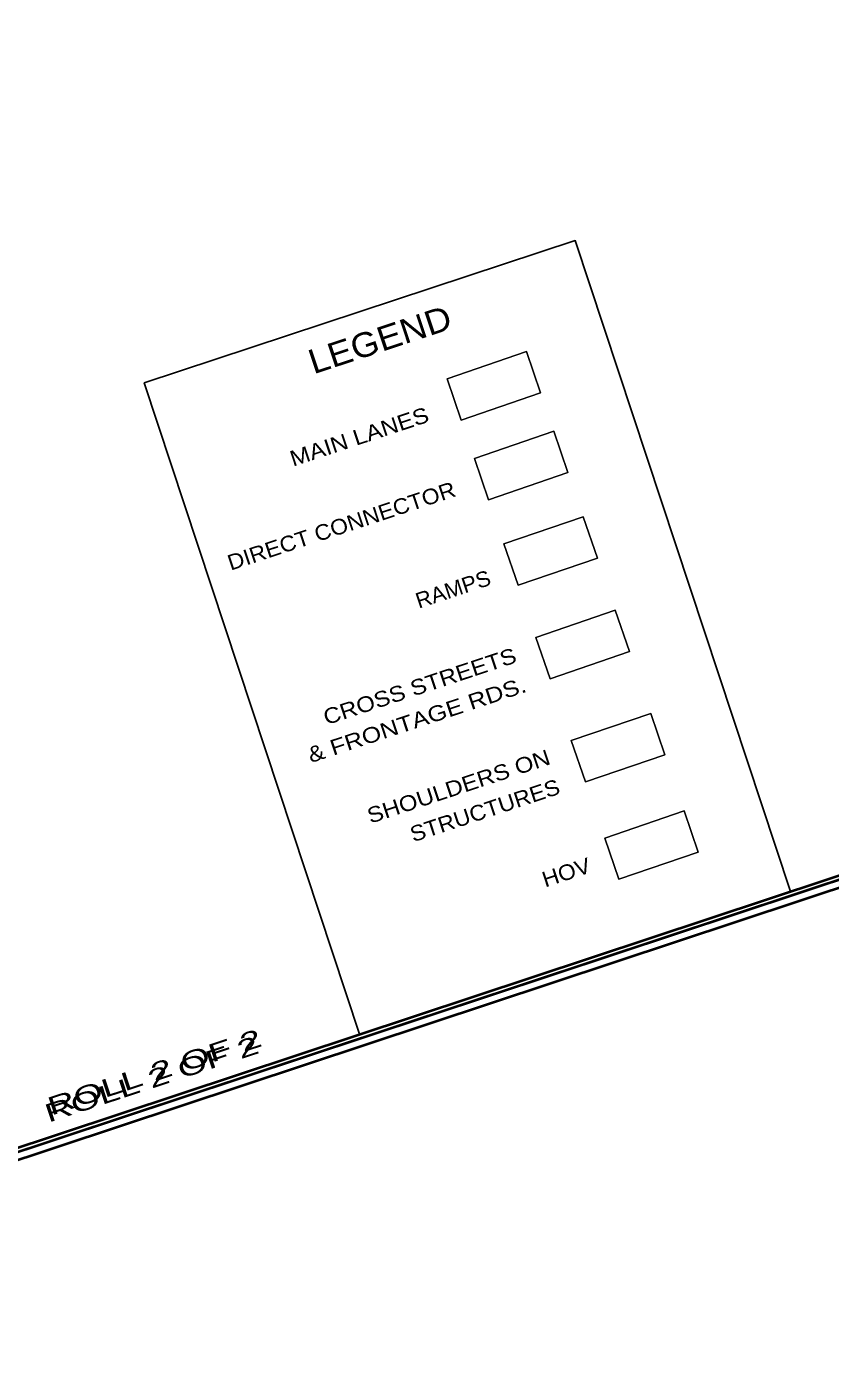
# Model space of a CAD drawing. Extents: x 2355803 to 2371254, y 6970215 to 6985302.
# Drawn here: x 2357680 to 2358715, y 6973568 to 6975290 of the extents above; entities that cross this region are included whole.
import ezdxf
from ezdxf.enums import TextEntityAlignment as Align

# ---------------------------------------------------------------- set-up
doc = ezdxf.new("R2010")
doc.units = 0
doc.header["$LTSCALE"] = 7.1
doc.layers.add('19', color=7, linetype='Continuous', lineweight=13)
doc.layers.add('8', color=7, linetype='Continuous', lineweight=13)

msp = doc.modelspace()

# ---------------------------------------------------------------- linework, layer by layer
at = {"layer": '19', "lineweight": 40}
msp.add_lwpolyline([(2371235.04, 6978344.083), (2356889.216, 6973586.555), (2355819.061, 6976813.747)], dxfattribs=at)
at = {"layer": '19', "lineweight": 25}
msp.add_lwpolyline([(2358108.756, 6973991.841), (2358663.88, 6974175.369), (2358386.548, 6975014.227), (2357831.424, 6974830.701)], close=True, dxfattribs=at)
at = {"layer": '19'}
for points in [[(2358323.762, 6974871.201), (2358342.014, 6974817.979), (2358239.818, 6974782.929), (2358221.564, 6974836.151)], [(2358221.564, 6974836.151), (2358239.818, 6974782.929), (2358342.014, 6974817.979), (2358323.762, 6974871.201)], [(2358358.966, 6974768.557), (2358377.22, 6974715.337), (2358275.02, 6974680.285), (2358256.768, 6974733.507)], [(2358256.768, 6974733.507), (2358275.02, 6974680.285), (2358377.22, 6974715.337), (2358358.966, 6974768.557)], [(2358396.778, 6974658.309), (2358415.03, 6974605.089), (2358312.832, 6974570.037), (2358294.578, 6974623.259)], [(2358294.578, 6974623.259), (2358312.832, 6974570.037), (2358415.03, 6974605.089), (2358396.778, 6974658.309)], [(2358438.066, 6974537.925), (2358456.318, 6974484.705), (2358354.122, 6974449.653), (2358335.868, 6974502.875)], [(2358335.868, 6974502.875), (2358354.122, 6974449.653), (2358456.318, 6974484.705), (2358438.066, 6974537.925)], [(2358483.7, 6974404.871), (2358501.954, 6974351.649), (2358399.754, 6974316.599), (2358381.5, 6974369.821)], [(2358381.5, 6974369.821), (2358399.754, 6974316.599), (2358501.954, 6974351.649), (2358483.7, 6974404.871)], [(2358526.726, 6974279.417), (2358544.98, 6974226.195), (2358442.782, 6974191.145), (2358424.53, 6974244.367)], [(2358424.53, 6974244.367), (2358442.782, 6974191.145), (2358544.98, 6974226.195), (2358526.726, 6974279.417)]]:
    msp.add_lwpolyline(points, close=True, dxfattribs=at)
at = {"layer": '8', "lineweight": 40}
for p, q in [((2371241.36, 6978340.911), (2356886.044, 6973580.235)), ((2371231.868, 6978337.763), (2356886.044, 6973580.235)), ((2371254, 6978334.567), (2356879.7, 6973567.595))]:
    msp.add_line(p, q, dxfattribs=at)
at = {"layer": '8', "lineweight": 25}
msp.add_lwpolyline([(2358108.756, 6973991.841), (2358663.88, 6974175.369), (2358386.548, 6975014.227), (2357831.424, 6974830.701)], close=True, dxfattribs=at)
at = {"layer": '8'}
for points in [[(2358323.762, 6974871.201), (2358342.014, 6974817.979), (2358239.818, 6974782.929), (2358221.564, 6974836.151)], [(2358221.564, 6974836.151), (2358239.818, 6974782.929), (2358342.014, 6974817.979), (2358323.762, 6974871.201)], [(2358358.966, 6974768.557), (2358377.22, 6974715.337), (2358275.02, 6974680.285), (2358256.768, 6974733.507)], [(2358256.768, 6974733.507), (2358275.02, 6974680.285), (2358377.22, 6974715.337), (2358358.966, 6974768.557)], [(2358396.778, 6974658.309), (2358415.03, 6974605.089), (2358312.832, 6974570.037), (2358294.578, 6974623.259)], [(2358294.578, 6974623.259), (2358312.832, 6974570.037), (2358415.03, 6974605.089), (2358396.778, 6974658.309)], [(2358438.066, 6974537.925), (2358456.318, 6974484.705), (2358354.122, 6974449.653), (2358335.868, 6974502.875)], [(2358335.868, 6974502.875), (2358354.122, 6974449.653), (2358456.318, 6974484.705), (2358438.066, 6974537.925)], [(2358483.7, 6974404.871), (2358501.954, 6974351.649), (2358399.754, 6974316.599), (2358381.5, 6974369.821)], [(2358381.5, 6974369.821), (2358399.754, 6974316.599), (2358501.954, 6974351.649), (2358483.7, 6974404.871)], [(2358526.726, 6974279.417), (2358544.98, 6974226.195), (2358442.782, 6974191.145), (2358424.53, 6974244.367)], [(2358424.53, 6974244.367), (2358442.782, 6974191.145), (2358544.98, 6974226.195), (2358526.726, 6974279.417)]]:
    msp.add_lwpolyline(points, close=True, dxfattribs=at)

# ---------------------------------------------------------------- texts
at = {"layer": '19', "width": 1.1}
msp.add_text('LEGEND', height=31.5, rotation=18.294, dxfattribs=at).set_placement((2358139.927, 6974871.607), align=Align.CENTER)
at = {"layer": '19'}
for s, width, p in [('MAIN LANES', 1.15, (2358199.992, 6974781.323)), ('DIRECT CONNECTOR', 1.1, (2358234.487, 6974685.214)), ('RAMPS', 1.05, (2358279.744, 6974571.166)), ('CROSS STREETS', 1.15, (2358312.735, 6974471.186)), ('& FRONTAGE RDS.', 1.2, (2358325.293, 6974433.208)), ('SHOULDERS ON', 1.15, (2358356.216, 6974339.936)), ('STRUCTURES', 1.1, (2358368.773, 6974301.955)), ('HOV', 1.1, (2358408.383, 6974200.566))]:
    msp.add_text(s, height=20, rotation=18.294, dxfattribs=dict(at, width=width)).set_placement(p, align=Align.RIGHT)
at = {"layer": '19', "width": 1.55}
msp.add_text('ROLL 2 OF 2', height=23.33, rotation=18.281, dxfattribs=at).set_placement((2357711.819, 6973886.59))
at = {"layer": '8', "width": 1.1}
msp.add_text('LEGEND', height=31.5, rotation=18.294, dxfattribs=at).set_placement((2358139.927, 6974871.607), align=Align.CENTER)
at = {"layer": '8'}
for s, width, p in [('MAIN LANES', 1.15, (2358199.992, 6974781.323)), ('DIRECT CONNECTOR', 1.1, (2358234.488, 6974685.214)), ('RAMPS', 1.05, (2358279.744, 6974571.166)), ('CROSS STREETS', 1.15, (2358312.735, 6974471.186)), ('& FRONTAGE RDS.', 1.2, (2358325.293, 6974433.208)), ('SHOULDERS ON', 1.15, (2358356.216, 6974339.936)), ('STRUCTURES', 1.1, (2358368.773, 6974301.955)), ('HOV', 1.1, (2358408.384, 6974200.566))]:
    msp.add_text(s, height=20, rotation=18.294, dxfattribs=dict(at, width=width)).set_placement(p, align=Align.RIGHT)
at = {"layer": '8', "width": 1.55}
msp.add_text('ROLL 2 OF 2', height=23.33, rotation=18.281, dxfattribs=at).set_placement((2357708.142, 6973877.499))

doc.saveas('drawing.dxf')
